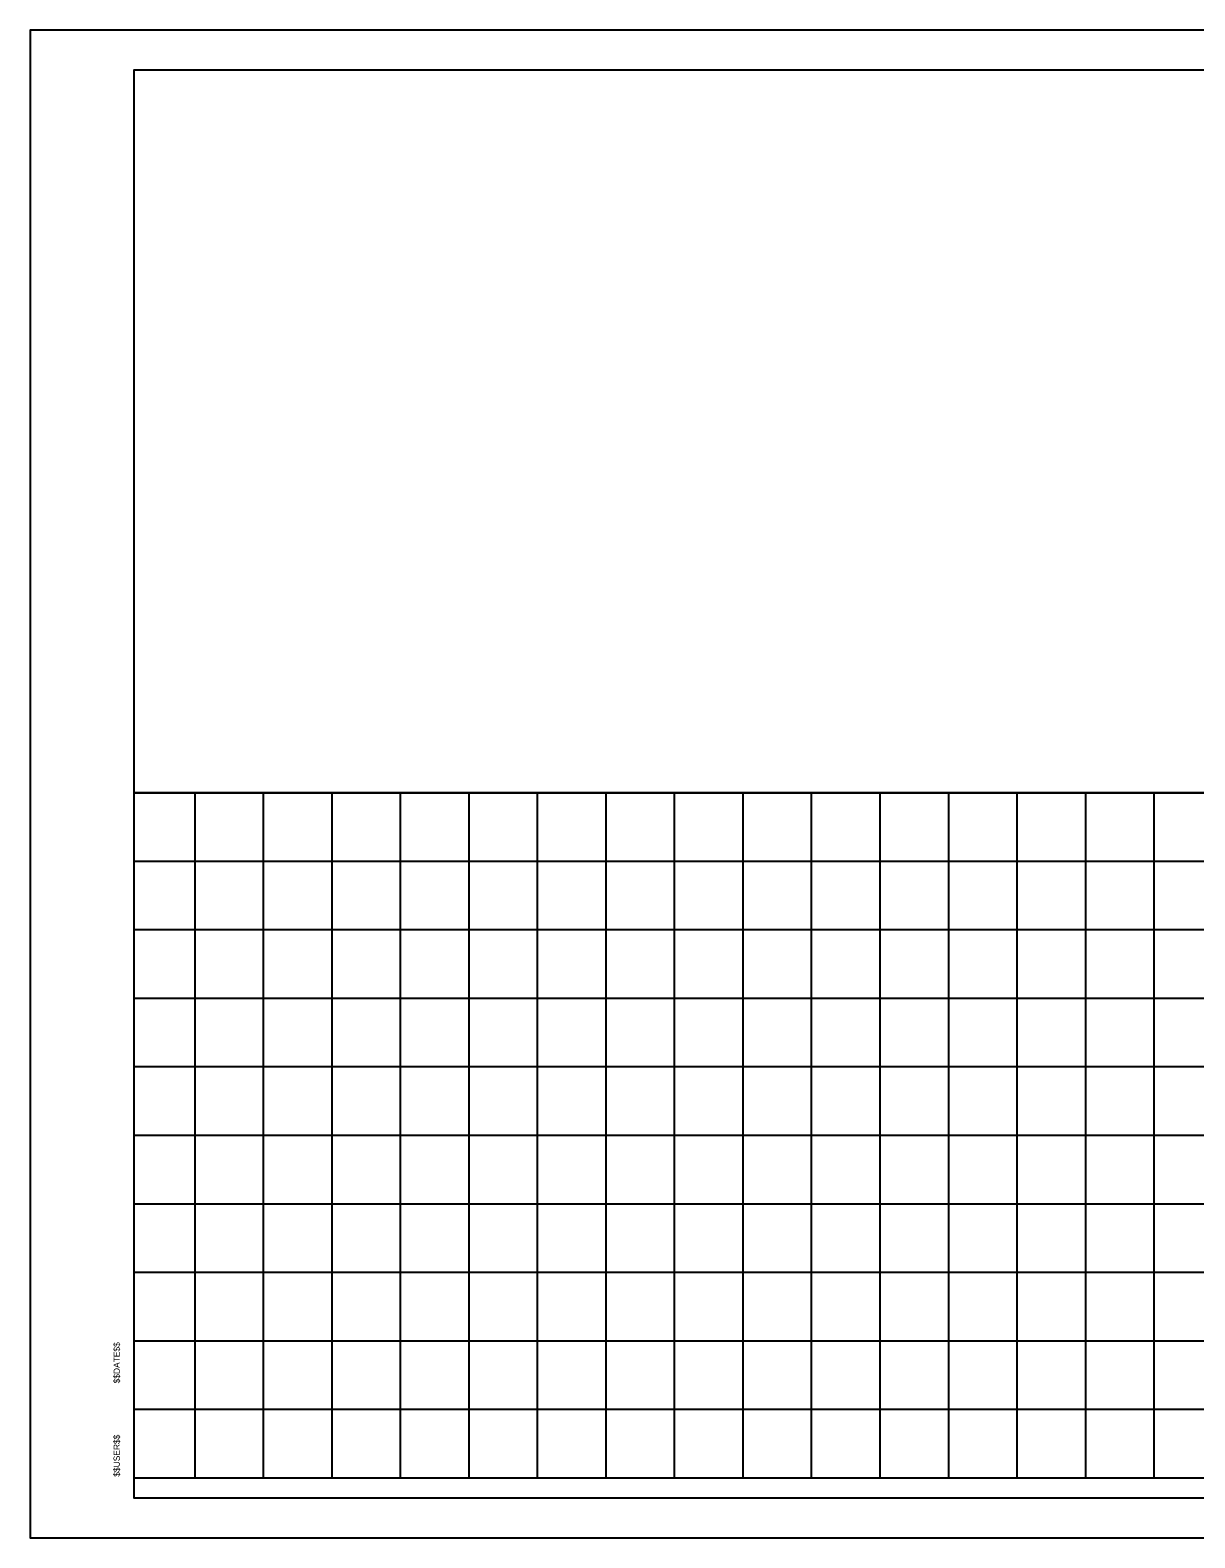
# Model space of a CAD drawing. Extents: x 0 to 1228743, y 0 to 152440.
# Drawn here: x 0 to 17, y 0 to 22 of the extents above; entities that cross this region are included whole.
import ezdxf

# ---------------------------------------------------------------- set-up
doc = ezdxf.new("R2010")
doc.units = 0
for name, color, linetype in [('G-TBLK', 7, 'Continuous'), ('R_Border', 7, 'Continuous'), ('R_Grid', 7, 'Continuous'), ('R_No Plot', 7, 'Continuous')]:
    doc.layers.add(name, color=color, linetype=linetype)

msp = doc.modelspace()

# ---------------------------------------------------------------- linework, layer by layer
at = {"layer": 'R_Border'}
for p, q in [((1.516, 0.577), (1.516, 21.423)), ((1.516, 21.423), (33.423, 21.423)), ((33.423, 0.577), (1.516, 0.577))]:
    msp.add_line(p, q, dxfattribs=at)
msp.add_lwpolyline([(34, 22), (0, 22), (0, 0), (34, 0)], close=True, dxfattribs=at)
at = {"layer": 'R_Grid'}
for p, q in [((33.423, 10.871), (1.516, 10.871)), ((2.407, 0.871), (2.407, 10.871)), ((3.407, 0.871), (3.407, 10.871)), ((4.407, 0.871), (4.407, 10.871)), ((5.407, 0.871), (5.407, 10.871)), ((6.407, 0.871), (6.407, 10.871)), ((7.407, 0.871), (7.407, 10.871)), ((8.407, 0.871), (8.407, 10.871)), ((9.407, 0.871), (9.407, 10.871)), ((10.407, 0.871), (10.407, 10.871)), ((11.407, 0.871), (11.407, 10.871)), ((12.407, 0.871), (12.407, 10.871)), ((13.407, 0.871), (13.407, 10.871)), ((14.407, 0.871), (14.407, 10.871)), ((15.407, 0.871), (15.407, 10.871)), ((16.407, 0.871), (16.407, 10.871)), ((33.423, 9.871), (1.516, 9.871)), ((33.423, 8.871), (1.516, 8.871)), ((33.423, 7.871), (1.516, 7.871)), ((33.423, 6.871), (1.516, 6.871)), ((33.423, 5.871), (1.516, 5.871)), ((33.423, 4.871), (1.516, 4.871)), ((33.423, 3.871), (1.516, 3.871)), ((33.423, 2.871), (1.516, 2.871)), ((33.423, 1.871), (1.516, 1.871)), ((33.423, 0.871), (1.516, 0.871)), ((33.423, 0.871), (1.516, 0.871))]:
    msp.add_line(p, q, dxfattribs=at)
at = {"layer": 'R_No Plot'}
msp.add_lwpolyline([(33.423, 17.405), (33.423, 10.871), (1.516, 10.871), (1.516, 21.423), (27.159, 21.423), (27.159, 20.435), (28.749, 20.435), (30.667, 20.435)], dxfattribs=at)
msp.add_lwpolyline([(1.516, 10.871), (33.423, 10.871), (33.423, 0.577), (1.516, 0.577)], close=True, dxfattribs=at)

# ---------------------------------------------------------------- texts
at = {"layer": 'G-TBLK'}
for s, p in [('$$DATE$$', (1.309, 2.254)), ('$$USER$$', (1.309, 0.892))]:
    msp.add_text(s, height=0.0918, rotation=90, dxfattribs=at).set_placement(p)

doc.saveas('drawing.dxf')
